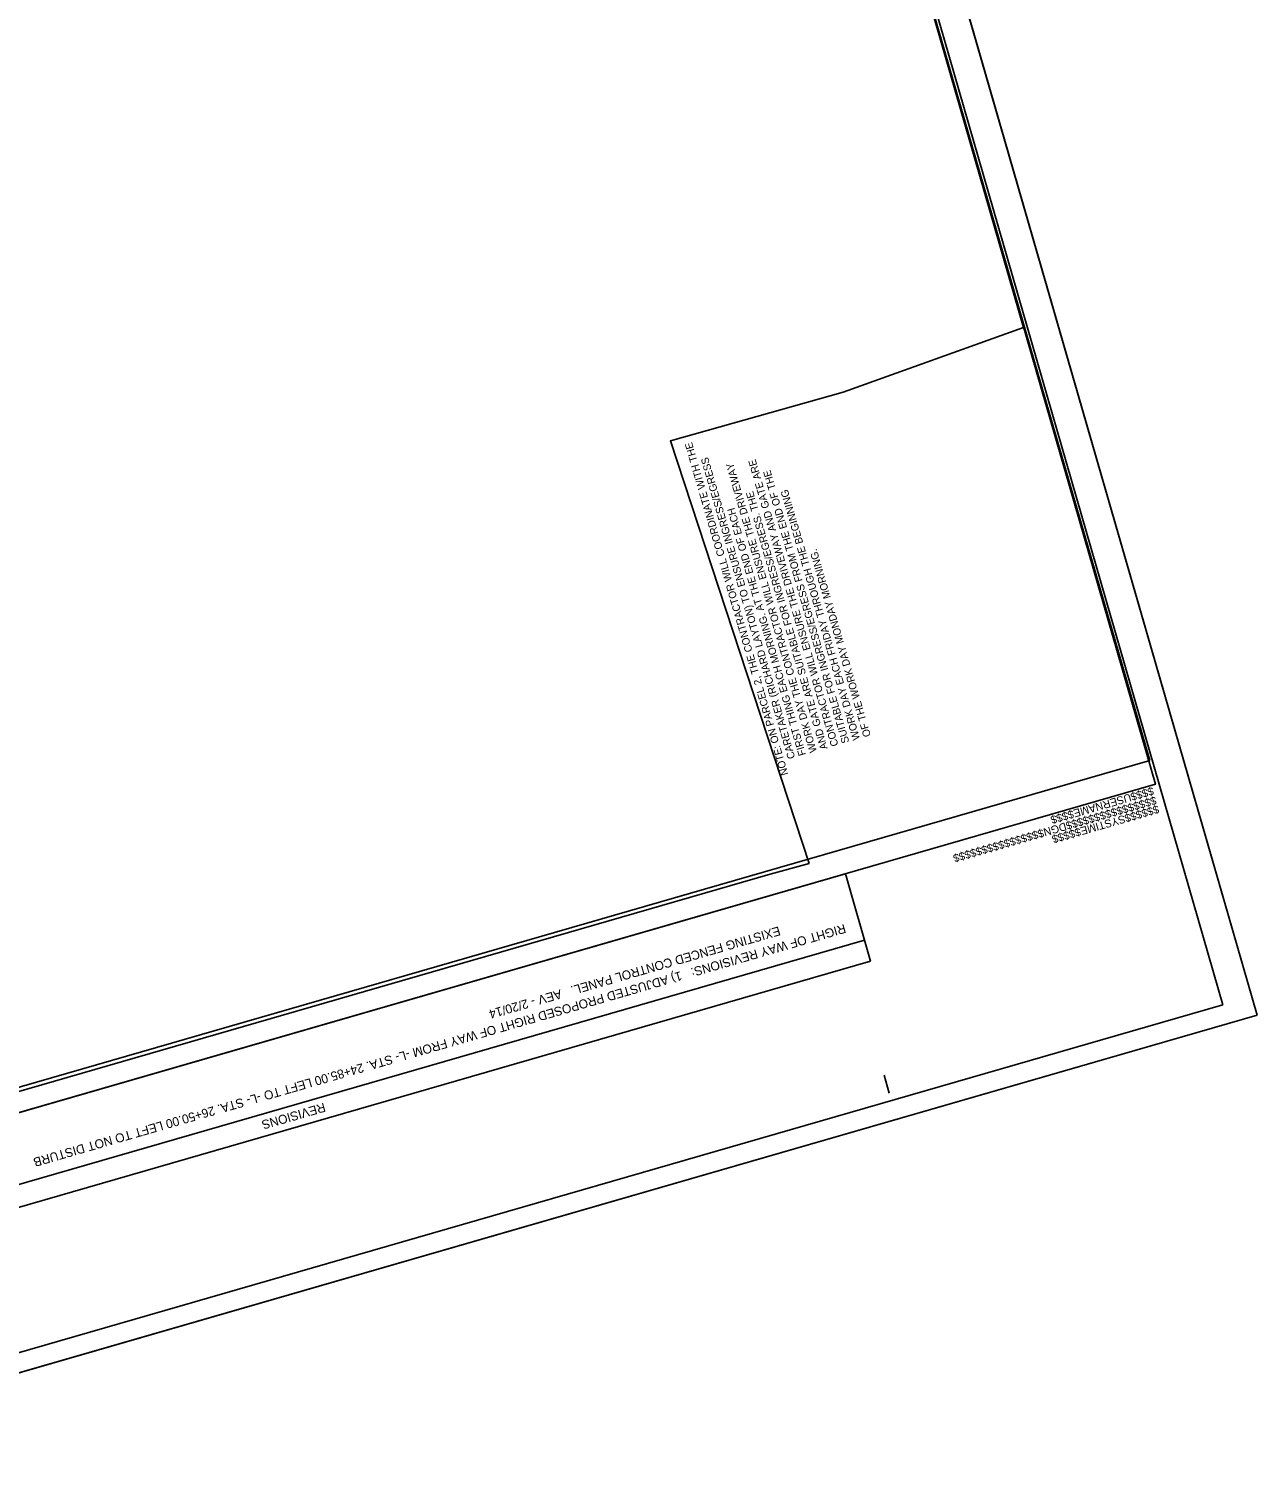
# Model space of a CAD drawing. Extents: x 2167139 to 2168658, y 842502 to 844423.
# Drawn here: x 2167839 to 2168658, y 842502 to 843463 of the extents above; entities that cross this region are included whole.
import ezdxf

# ---------------------------------------------------------------- set-up
doc = ezdxf.new("R2010")
doc.units = 0
for name, color, linetype in [('Prop Dimension Text', 7, 'Continuous'), ('Sheet Block Revision CELL', 7, 'Continuous'), ('Sheet Clip Boundary CELL', 7, 'Continuous'), ('Sheet Cutting Line CELL', 7, 'Continuous'), ('Sheet Layout Plan Border', 7, 'Continuous'), ('Sheet Plan CELL', 7, 'Continuous'), ('Sheet Plan Layout CELL', 7, 'Continuous'), ('Sheet Plot Border Inside CELL', 7, 'Continuous'), ('Sheet Plot Border Outside CELL', 7, 'Continuous')]:
    doc.layers.add(name, color=color, linetype=linetype)

msp = doc.modelspace()

# ---------------------------------------------------------------- linework, layer by layer
at = {"layer": 'Sheet Block Revision CELL'}
msp.add_line((2168396.31, 842855.61), (2167636.7, 842636.29), dxfattribs=at)
msp.add_lwpolyline([(2168400.37, 842841.64), (2167640.74, 842622.33), (2167623.93, 842680.48), (2168383.55, 842899.8)], close=True, dxfattribs=at)
at = {"layer": 'Sheet Clip Boundary CELL'}
msp.add_lwpolyline([(2168333.42, 842899.61), (2168359.34, 842906.72), (2168266.95, 843188.11), (2168382.06, 843220.66), (2168502.28, 843263.66), (2168187.91, 844352.53), (2167382.3, 844119.94), (2167434.8, 843938.11), (2167231.61, 843879.44), (2167577.57, 842681.16)], close=True, dxfattribs=at)
at = {"layer": 'Sheet Cutting Line CELL'}
for p, q in [((2168657.93, 842805.71), (2168190.95, 844423.15)), ((2167605.9, 842501.98), (2168657.93, 842805.71))]:
    msp.add_line(p, q, dxfattribs=at)
at = {"layer": 'Sheet Layout Plan Border'}
msp.add_lwpolyline([(2168586.35, 842975.21), (2168177.55, 844388.42), (2167371.94, 844155.82), (2167434.8, 843938.11), (2167231.61, 843879.44), (2167577.55, 842683.96)], close=True, dxfattribs=at)
at = {"layer": 'Sheet Plan CELL'}
for p, q in [((2168590.12, 842959.42), (2168590.12, 842959.42)), ((2168412.74, 842753.67), (2168409.29, 842765.68))]:
    msp.add_line(p, q, dxfattribs=at)
for points in [[(2167165.23, 844109.34), (2167581.32, 842668.17), (2168590.12, 842959.42), (2168174.04, 844400.57)], [(2168590.12, 842959.42), (2167581.35, 842668.15), (2167220.72, 843917.11), (2167364.89, 843958.75), (2167309.41, 844150.94), (2168174.04, 844400.57)]]:
    msp.add_lwpolyline(points, close=True, dxfattribs=at)
at = {"layer": 'Sheet Plan Layout CELL'}
msp.add_lwpolyline([(2167581.35, 842668.15), (2168590.12, 842959.42), (2168174.04, 844400.56), (2167368.43, 844167.97), (2167434.8, 843938.11), (2167231.61, 843879.44)], close=True, dxfattribs=at)
at = {"layer": 'Sheet Plot Border Inside CELL'}
msp.add_lwpolyline([(2168635.11, 842812.65), (2168172.98, 844413.26), (2167159.38, 844120.64), (2167621.51, 842520.01)], close=True, dxfattribs=at)
at = {"layer": 'Sheet Plot Border Outside CELL'}
msp.add_lwpolyline([(2168657.93, 842805.71), (2168190.95, 844423.15), (2167138.92, 844119.41), (2167605.9, 842501.98)], close=True, dxfattribs=at)

# ---------------------------------------------------------------- texts
at = {"layer": 'Prop Dimension Text'}
for s, p in [('NOTE: ON PARCEL 2, THE CONTRACTOR WILL COORDINATE WITH THE ', (2168345.54, 842966.11)), ('     CARETAKER (RICHARD LAYTON) TO ENSURE INGRESS/EGRESS ', (2168352.74, 842968.2)), ('     CONTRACTOR WILL ENSURE THE DRIVEWAY AND GATE ARE ', (2168381.55, 842976.56)), ('     WORK DAY THE CONTRACTOR WILL ENSURE THE DRIVEWAY ', (2168367.15, 842972.38)), ('     SUITABLE FOR INGRESS/EGRESS FROM THE END OF THE ', (2168388.76, 842978.65)), ('     WORK DAY EACH FRIDAY THROUGH THE BEGINNING ', (2168395.96, 842980.74)), ('     AND GATE ARE SUITABLE FOR INGRESS/EGRESS. THE ', (2168374.35, 842974.47)), ('     FIRST THING EACH MORNING. AT THE END OF EACH ', (2168359.94, 842970.29)), ('     OF THE WORK DAY MONDAY MORNING. ', (2168403.16, 842982.83))]:
    msp.add_text(s, height=5, rotation=106.18713, dxfattribs=at).set_placement(p)
at = {"layer": 'Sheet Block Revision CELL'}
for s, p in [('RIGHT OF WAY REVISIONS:   1) ADJUSTED PROPOSED RIGHT OF WAY FROM -L- STA. 24+85.00 LEFT TO -L- STA. 26+50.00 LEFT TO NOT DISTURB', (2168382.8, 842866.49)), ('                   EXISTING FENCED CONTROL PANEL.   AEV - 2/20/14                                                               ', (2168379.83, 842876.64)), ('REVISIONS', (2168036.04, 842747.38))]:
    msp.add_text(s, height=6, rotation=196.1042, dxfattribs=at).set_placement(p)
at = {"layer": 'Sheet Plan CELL'}
for s, p in [('$$$$USERNAME$$$$', (2168588.14, 842957.72)), ('$$$$$$$$$$$$$$$$DGN$$$$$$$$$$$$$$$$', (2168589.97, 842951.43)), ('$$$$$$SYSTIME$$$$$', (2168591.68, 842945.6))]:
    msp.add_text(s, height=5.25, rotation=196.10421, dxfattribs=at).set_placement(p)

doc.saveas('drawing.dxf')
